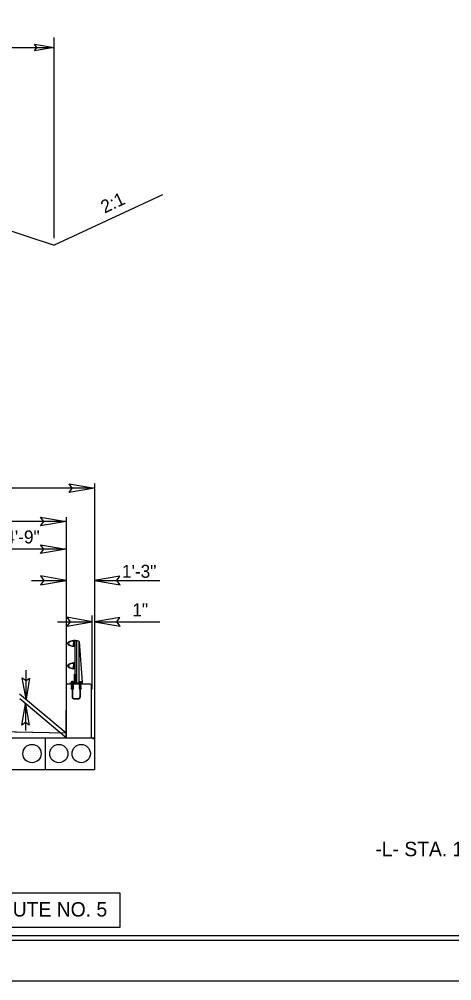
# Model space of a CAD drawing. Extents: x 1718167 to 1721223, y 797898 to 799800.
# Drawn here: x 1719936 to 1720176, y 798024 to 798557 of the extents above; entities that cross this region are included whole.
import ezdxf

# ---------------------------------------------------------------- set-up
doc = ezdxf.new("R2010")
doc.units = 0
for name, color, linetype in [('Default', 7, 'Continuous'), ('Old_Level_1', 7, 'Continuous'), ('Old_Level_18', 7, 'Continuous'), ('Old_Level_2', 7, 'Continuous'), ('Prop Dimension Text', 7, 'Continuous'), ('Prop Shade Heavy', 7, 'Continuous'), ('Prop Terminator CELL', 7, 'Continuous'), ('Sheet Cutting Line CELL', 7, 'Continuous'), ('Sheet Plot Border Inside CELL', 7, 'Continuous'), ('Sheet Plot Border Outside CELL', 7, 'Continuous'), ('Sheet Typical CELL', 7, 'Continuous'), ('Typical Bridge Rail Two Bar CELL', 7, 'Continuous'), ('Typical Pavement Slope CELL', 7, 'Continuous'), ('Typical Slope Point Local CELL', 7, 'Continuous'), ('Typical Terminator CELL', 7, 'Continuous'), ('Typical Text General CELL', 7, 'Continuous'), ('Typical Text Label CELL', 7, 'Continuous')]:
    doc.layers.add(name, color=color, linetype=linetype)

msp = doc.modelspace()

# ---------------------------------------------------------------- linework, layer by layer
at = {"layer": 'Old_Level_1'}
for p, q in [((1719955.77, 798435.68), (1719955.79, 798546.84)), ((1719900.76, 798541.34), (1719955.79, 798541.33)), ((1719900.75, 798450.13), (1719955.77, 798431.77)), ((1719962.39, 798263.48), (1719915.89, 798263.48)), ((1719652.48, 798158.9), (1719978.23, 798158.9)), ((1719978.23, 798158.9), (1719978.23, 798141.4)), ((1719652.48, 798141.4), (1719978.23, 798141.4))]:
    msp.add_line(p, q, dxfattribs=at)
at = {"layer": 'Old_Level_18'}
msp.add_line((1719950.96, 798141.4), (1719950.96, 798158.9), dxfattribs=at)
for centre in [(1719943.58, 798150.23), (1719958.42, 798150.23), (1719970.8, 798150.23)]:
    msp.add_circle(centre, 5.06, dxfattribs=at)
at = {"layer": 'Old_Level_2'}
for p, q in [((1719978.22, 798299.76), (1719978.22, 798158.26)), ((1719978.22, 798297.26), (1719652.48, 798297.26)), ((1719962.39, 798278.8), (1719668.32, 798278.8)), ((1719962.39, 798281.22), (1719962.39, 798174.01)), ((1719943.19, 798246.15), (1719962.39, 798246.15)), ((1719978.22, 798246.15), (1720014.4, 798246.15)), ((1719976.94, 798185.96), (1719976.94, 798226.74)), ((1719957.74, 798223.27), (1719976.94, 798223.27)), ((1719978.23, 798223.27), (1720014.41, 798223.27))]:
    msp.add_line(p, q, dxfattribs=at)
at = {"layer": 'Prop Dimension Text'}
for p, q in [((1719962.39, 798161.47), (1719936.7, 798183.2)), ((1719962.39, 798158.9), (1719936.83, 798180.52))]:
    msp.add_line(p, q, dxfattribs=at)
at = {"layer": 'Prop Shade Heavy'}
msp.add_lwpolyline([(1719815.89, 798163.35), (1719815.89, 798158.9), (1719962.39, 798158.9), (1719962.39, 798161.47), (1719815.89, 798164.42)], close=True, dxfattribs=at)
at = {"layer": 'Prop Terminator CELL'}
msp.add_lwpolyline([(1719944.99, 798543.19), (1719955.79, 798541.33), (1719944.93, 798539.41), (1719946.31, 798541.33)], close=True, dxfattribs=at)
at = {"layer": 'Sheet Cutting Line CELL'}
msp.add_line((1718866, 798024.37), (1720550, 798024.37), dxfattribs=at)
at = {"layer": 'Sheet Plot Border Inside CELL'}
msp.add_lwpolyline([(1720545.5, 799101.92), (1718879, 799101.92), (1718879, 798046.82), (1720545.5, 798046.82)], close=True, dxfattribs=at)
at = {"layer": 'Sheet Plot Border Outside CELL'}
msp.add_lwpolyline([(1720550, 799124.37), (1718866, 799124.37), (1718866, 798024.37), (1720550, 798024.37)], close=True, dxfattribs=at)
at = {"layer": 'Sheet Typical CELL'}
msp.add_lwpolyline([(1720533, 799099.37), (1719033, 799099.37), (1719033, 798049.37), (1720533, 798049.37)], close=True, dxfattribs=at)
at = {"layer": 'Typical Bridge Rail Two Bar CELL'}
for p, q in [((1719966.59, 798212.45), (1719966.59, 798211.17)), ((1719966.59, 798209.89), (1719966.59, 798211.17)), ((1719967.38, 798212.84), (1719968.32, 798212.84)), ((1719967.38, 798189.29), (1719967.38, 798212.84)), ((1719969.74, 798212.37), (1719968.32, 798212.84)), ((1719968.32, 798189.29), (1719968.32, 798212.84)), ((1719969.74, 798189.29), (1719969.74, 798212.37)), ((1719969.74, 798212.37), (1719971.39, 798189.76)), ((1719966.59, 798200.1), (1719966.59, 798198.83)), ((1719966.59, 798197.55), (1719966.59, 798198.83)), ((1719969.74, 798201.57), (1719969.8, 798201.57)), ((1719962.39, 798188.21), (1719963, 798188.82)), ((1719962.39, 798188.21), (1719962.39, 798158.9)), ((1719963, 798188.82), (1719975.76, 798188.82)), ((1719965.24, 798188.37), (1719966.49, 798188.37)), ((1719965.24, 798188.23), (1719966.49, 798188.23)), ((1719965.24, 798187.81), (1719965.76, 798187.81)), ((1719965.24, 798187.68), (1719965.76, 798187.68)), ((1719965.24, 798187.26), (1719965.76, 798187.26)), ((1719965.51, 798188.09), (1719965.76, 798188.09)), ((1719965.51, 798187.95), (1719965.76, 798187.95)), ((1719965.51, 798187.53), (1719965.76, 798187.53)), ((1719965.51, 798187.4), (1719965.76, 798187.4)), ((1719965.55, 798188.37), (1719965.55, 798189.41)), ((1719965.57, 798189.92), (1719965.57, 798190.37)), ((1719965.57, 798190.37), (1719966.11, 798190.37)), ((1719965.76, 798188.09), (1719965.96, 798188.09)), ((1719965.76, 798188.09), (1719965.76, 798181.46)), ((1719965.96, 798188.09), (1719966.21, 798188.09)), ((1719965.96, 798188.09), (1719965.96, 798181.46)), ((1719965.96, 798187.95), (1719966.21, 798187.95)), ((1719965.96, 798187.81), (1719966.49, 798187.81)), ((1719965.96, 798187.68), (1719966.49, 798187.68)), ((1719965.96, 798187.53), (1719966.21, 798187.53)), ((1719965.96, 798187.4), (1719966.21, 798187.4)), ((1719965.96, 798187.26), (1719966.49, 798187.26)), ((1719966.11, 798190.37), (1719966.11, 798189.92)), ((1719966.14, 798188.37), (1719966.14, 798189.41)), ((1719969.59, 798188.37), (1719970.84, 798188.37)), ((1719969.59, 798188.23), (1719970.84, 798188.23)), ((1719969.59, 798187.81), (1719970.11, 798187.81)), ((1719969.59, 798187.68), (1719970.11, 798187.68)), ((1719969.59, 798187.26), (1719970.11, 798187.26)), ((1719969.87, 798188.09), (1719970.11, 798188.09)), ((1719969.87, 798187.95), (1719970.11, 798187.95)), ((1719969.87, 798187.53), (1719970.11, 798187.53)), ((1719969.87, 798187.4), (1719970.11, 798187.4)), ((1719969.93, 798189.8), (1719969.93, 798190.24)), ((1719969.93, 798190.24), (1719970.47, 798190.24)), ((1719969.94, 798188.25), (1719969.94, 798189.29)), ((1719970.11, 798188.09), (1719970.32, 798188.09)), ((1719970.11, 798188.09), (1719970.11, 798181.46)), ((1719970.32, 798188.09), (1719970.57, 798188.09)), ((1719970.32, 798188.09), (1719970.32, 798181.46)), ((1719970.32, 798187.95), (1719970.57, 798187.95)), ((1719970.32, 798187.81), (1719970.84, 798187.81)), ((1719970.32, 798187.68), (1719970.84, 798187.68)), ((1719970.32, 798187.53), (1719970.57, 798187.53)), ((1719970.32, 798187.4), (1719970.57, 798187.4)), ((1719970.32, 798187.26), (1719970.84, 798187.26)), ((1719970.47, 798190.24), (1719970.47, 798189.8)), ((1719970.48, 798188.25), (1719970.48, 798189.29)), ((1719971.34, 798190.03), (1719971.34, 798190.44)), ((1719971.39, 798189.29), (1719971.39, 798189.76)), ((1719975.76, 798188.82), (1719976.37, 798188.21)), ((1719976.37, 798188.21), (1719976.37, 798158.9)), ((1719965.24, 798187.12), (1719965.76, 798187.12)), ((1719965.24, 798186.7), (1719965.76, 798186.7)), ((1719965.24, 798186.56), (1719965.76, 798186.56)), ((1719965.24, 798186.15), (1719965.76, 798186.15)), ((1719965.24, 798186.01), (1719965.76, 798186.01)), ((1719965.51, 798186.98), (1719965.76, 798186.98)), ((1719965.51, 798186.84), (1719965.76, 798186.84)), ((1719965.51, 798186.42), (1719965.76, 798186.42)), ((1719965.51, 798186.29), (1719965.76, 798186.29)), ((1719965.96, 798187.12), (1719966.49, 798187.12)), ((1719965.96, 798186.98), (1719966.21, 798186.98)), ((1719965.96, 798186.84), (1719966.21, 798186.84)), ((1719965.96, 798186.7), (1719966.49, 798186.7)), ((1719965.96, 798186.56), (1719966.49, 798186.56)), ((1719965.96, 798186.42), (1719966.21, 798186.42)), ((1719965.96, 798186.29), (1719966.21, 798186.29)), ((1719965.96, 798186.15), (1719966.49, 798186.15)), ((1719965.96, 798186.01), (1719966.49, 798186.01)), ((1719969.59, 798187.12), (1719970.11, 798187.12)), ((1719969.59, 798186.7), (1719970.11, 798186.7)), ((1719969.59, 798186.56), (1719970.11, 798186.56)), ((1719969.59, 798186.15), (1719970.11, 798186.15)), ((1719969.59, 798186.01), (1719970.11, 798186.01)), ((1719969.87, 798186.98), (1719970.11, 798186.98)), ((1719969.87, 798186.84), (1719970.11, 798186.84)), ((1719969.87, 798186.42), (1719970.11, 798186.42)), ((1719969.87, 798186.29), (1719970.11, 798186.29)), ((1719970.32, 798187.12), (1719970.84, 798187.12)), ((1719970.32, 798186.98), (1719970.57, 798186.98)), ((1719970.32, 798186.84), (1719970.57, 798186.84)), ((1719970.32, 798186.7), (1719970.84, 798186.7)), ((1719970.32, 798186.56), (1719970.84, 798186.56)), ((1719970.32, 798186.42), (1719970.57, 798186.42)), ((1719970.32, 798186.29), (1719970.57, 798186.29)), ((1719970.32, 798186.15), (1719970.84, 798186.15)), ((1719970.32, 798186.01), (1719970.84, 798186.01)), ((1719966.63, 798180.79), (1719969.44, 798180.79)), ((1719966.63, 798180.58), (1719969.44, 798180.58)), ((1719962.39, 798158.9), (1719976.25, 798158.9)), ((1719976.25, 798158.9), (1719977.26, 798158.9)), ((1719977.87, 798158.23), (1719977.26, 798158.9))]:
    msp.add_line(p, q, dxfattribs=at)
for points in [[(1719967.38, 798209.54), (1719967.38, 798210.15), (1719967.13, 798210.15), (1719967.13, 798210.04), (1719967.15, 798210.04), (1719967.15, 798209.79), (1719966.74, 798209.79), (1719966.69, 798210.18), (1719966.69, 798211.17), (1719966.69, 798212.15), (1719966.74, 798212.54), (1719967.15, 798212.54), (1719967.15, 798212.29), (1719967.13, 798212.29), (1719967.13, 798212.19), (1719967.38, 798212.19), (1719967.38, 798212.8)], [(1719967.38, 798197.19), (1719967.38, 798197.81), (1719967.13, 798197.81), (1719967.13, 798197.71), (1719967.15, 798197.71), (1719967.15, 798197.45), (1719966.74, 798197.45), (1719966.69, 798197.84), (1719966.69, 798198.83), (1719966.69, 798199.81), (1719966.74, 798200.2), (1719967.15, 798200.2), (1719967.15, 798199.95), (1719967.13, 798199.95), (1719967.13, 798199.85), (1719967.38, 798199.85), (1719967.38, 798200.46)], [(1719964.96, 798188.82), (1719964.96, 798189.41), (1719967.14, 798189.41), (1719967.14, 798194.24), (1719967.38, 798194.24), (1719967.38, 798189.29), (1719971.28, 798189.29), (1719971.28, 798189.64), (1719971.39, 798189.64), (1719971.39, 798188.82), (1719969.51, 798188.82), (1719969.51, 798189.15), (1719967.61, 798189.15), (1719967.61, 798188.82), (1719964.96, 798188.82)], [(1719965.23, 798188.37), (1719965.23, 798188.23), (1719965.51, 798188.09), (1719965.51, 798187.95), (1719965.23, 798187.81), (1719965.23, 798187.68), (1719965.51, 798187.53), (1719965.51, 798187.4), (1719965.23, 798187.26), (1719965.23, 798187.12), (1719965.51, 798186.98), (1719965.51, 798186.84), (1719965.23, 798186.7), (1719965.23, 798186.56), (1719965.51, 798186.42), (1719965.51, 798186.29), (1719965.23, 798186.15), (1719965.23, 798186.01)], [(1719965.3, 798189.41), (1719965.3, 798189.51), (1719965.83, 798189.51), (1719966.37, 798189.51), (1719966.37, 798189.41)], [(1719965.44, 798189.51), (1719965.44, 798189.85), (1719965.51, 798189.92), (1719966.17, 798189.92), (1719966.24, 798189.85), (1719966.24, 798189.51), (1719965.44, 798189.51), (1719965.71, 798189.51), (1719965.71, 798189.85), (1719965.64, 798189.92), (1719965.71, 798189.85), (1719965.78, 798189.92), (1719965.91, 798189.92), (1719965.98, 798189.85), (1719965.98, 798189.51), (1719965.98, 798189.85), (1719966.04, 798189.92)], [(1719966.49, 798188.37), (1719966.49, 798188.23), (1719966.21, 798188.09), (1719966.21, 798187.95), (1719966.49, 798187.81), (1719966.49, 798187.68), (1719966.21, 798187.53), (1719966.21, 798187.4), (1719966.49, 798187.26), (1719966.49, 798187.12), (1719966.21, 798186.98), (1719966.21, 798186.84), (1719966.49, 798186.7), (1719966.49, 798186.56), (1719966.21, 798186.42), (1719966.21, 798186.29), (1719966.49, 798186.15), (1719966.49, 798186.01)], [(1719969.59, 798188.37), (1719969.59, 798188.23), (1719969.87, 798188.09), (1719969.87, 798187.95), (1719969.59, 798187.81), (1719969.59, 798187.68), (1719969.87, 798187.53), (1719969.87, 798187.4), (1719969.59, 798187.26), (1719969.59, 798187.12), (1719969.87, 798186.98), (1719969.87, 798186.84), (1719969.59, 798186.7), (1719969.59, 798186.56), (1719969.87, 798186.42), (1719969.87, 798186.29), (1719969.59, 798186.15), (1719969.59, 798186.01)], [(1719969.67, 798189.29), (1719969.67, 798189.39), (1719970.2, 798189.39), (1719970.74, 798189.39), (1719970.74, 798189.29)], [(1719969.81, 798189.39), (1719969.81, 798189.73), (1719969.87, 798189.8), (1719970.53, 798189.8), (1719970.6, 798189.73), (1719970.6, 798189.39), (1719969.81, 798189.39), (1719970.07, 798189.39), (1719970.07, 798189.73), (1719970, 798189.8), (1719970.07, 798189.73), (1719970.13, 798189.8), (1719970.27, 798189.8), (1719970.34, 798189.73), (1719970.34, 798189.39), (1719970.34, 798189.73), (1719970.41, 798189.8)], [(1719970.84, 798188.37), (1719970.84, 798188.23), (1719970.57, 798188.09), (1719970.57, 798187.95), (1719970.84, 798187.81), (1719970.84, 798187.68), (1719970.57, 798187.53), (1719970.57, 798187.4), (1719970.84, 798187.26), (1719970.84, 798187.12), (1719970.57, 798186.98), (1719970.57, 798186.84), (1719970.84, 798186.7), (1719970.84, 798186.56), (1719970.57, 798186.42), (1719970.57, 798186.29), (1719970.84, 798186.15), (1719970.84, 798186.01)]]:
    msp.add_lwpolyline(points, dxfattribs=at)
for centre in [(1719965.34, 798186.35), (1719970.73, 798186.35)]:
    msp.add_circle(centre, 0.104, dxfattribs=at)
for centre, radius, start, end in [((1719966.49, 798212.45), 0.0979, 0, 90), ((1719966.49, 798209.89), 0.0979, 270, 360), ((1719966.49, 798200.11), 0.0979, 0, 90), ((1719966.49, 798197.55), 0.0979, 270, 360), ((1719966.63, 798181.46), 0.876, 180, 270), ((1719966.63, 798181.46), 0.667, 180, 270), ((1719969.44, 798181.46), 0.667, 270, 0), ((1719969.44, 798181.46), 0.876, 270, 0)]:
    msp.add_arc(centre, radius, start, end, dxfattribs=at)
for centre, major_axis, ratio, start_param, end_param in [((1719967.38, 798211.17), (-4.18, 0), 0.39036, 4.712404, 6.283584), ((1719967.38, 798211.17), (-4.18, 0), 0.39036, 0.000398, 1.570782), ((1719966.49, 798211.17), (-2.78, 0), 0.495501, 4.712489, 6.283652), ((1719966.49, 798211.17), (-2.78, 0), 0.495501, 0.000467, 1.570696), ((1719967.38, 798198.83), (-4.18, 0), 0.39036, 4.712404, 6.283584), ((1719967.38, 798198.83), (-4.18, 0), 0.39036, 0.000398, 1.570782), ((1719966.49, 798198.83), (-2.78, 0), 0.495501, 4.712489, 6.283652), ((1719966.49, 798198.83), (-2.78, 0), 0.495501, 0.000467, 1.570696)]:
    msp.add_ellipse(centre, major_axis=major_axis, ratio=ratio, start_param=start_param, end_param=end_param, dxfattribs=at)
at = {"layer": 'Typical Pavement Slope CELL'}
for q in [(1719962.39, 798174.01), (1719815.89, 798164.42)]:
    msp.add_line((1719962.39, 798161.47), q, dxfattribs=at)
at = {"layer": 'Typical Slope Point Local CELL'}
msp.add_line((1720015.77, 798459.76), (1719955.77, 798431.77), dxfattribs=at)
at = {"layer": 'Typical Terminator CELL'}
for points in [[(1719964.16, 798299.68), (1719978.22, 798297.26), (1719964.09, 798294.76), (1719965.88, 798297.26)], [(1719948.33, 798281.22), (1719962.39, 798278.8), (1719948.26, 798276.3), (1719950.05, 798278.8)], [(1719948.33, 798265.9), (1719962.39, 798263.48), (1719948.26, 798260.98), (1719950.05, 798263.48)], [(1719948.33, 798243.73), (1719962.39, 798246.15), (1719948.26, 798248.65), (1719950.05, 798246.15)], [(1719992.28, 798248.57), (1719978.22, 798246.15), (1719992.36, 798243.65), (1719990.57, 798246.15)], [(1719962.88, 798220.85), (1719976.94, 798223.27), (1719962.8, 798225.77), (1719964.6, 798223.27)], [(1719992.29, 798225.69), (1719978.23, 798223.27), (1719992.37, 798220.77), (1719990.57, 798223.27)], [(1719942.25, 798192.05), (1719940.23, 798180.33), (1719938.15, 798192.11), (1719940.23, 798190.62)], [(1719937.96, 798166.02), (1719939.98, 798177.74), (1719942.06, 798165.96), (1719939.98, 798167.45)]]:
    msp.add_lwpolyline(points, close=True, dxfattribs=at)
at = {"layer": 'Typical Text General CELL'}
for p, q in [((1719940.23, 798180.33), (1719940.23, 798196.4)), ((1719939.98, 798177.74), (1719939.98, 798163.03))]:
    msp.add_line(p, q, dxfattribs=at)
at = {"layer": 'Typical Text Label CELL'}
msp.add_lwpolyline([(1719662.34, 798073.04), (1719992.26, 798073.04), (1719992.26, 798053.81), (1719662.34, 798053.81)], close=True, dxfattribs=at)

# ---------------------------------------------------------------- texts
at = {"layer": 'Default'}
for s, p in [('-L- STA. 17+54.06 (BEGIN BRIDGE) TO 18+76.56 (END BRIDGE)', (1720133.7, 798093.36)), ('SR 1193, BAKER RD IS A DESIGNATED BICYCLE ROUTE NO. 5', (1719667.13, 798059.94))]:
    msp.add_text(s, height=8, dxfattribs=at).set_placement(p)
at = {"layer": 'Old_Level_1'}
for s, p in [('4\'-9"', (1719928.74, 798266.64)), ('1\'-3"', (1719993.37, 798247.61)), ('1"', (1719999.11, 798226.25))]:
    msp.add_text(s, height=7.161, dxfattribs=at).set_placement(p)
at = {"layer": 'Typical Slope Point Local CELL'}
msp.add_text('2:1', height=7.161, rotation=25.0018, dxfattribs=at).set_placement((1719983.73, 798449.31))

doc.saveas('drawing.dxf')
